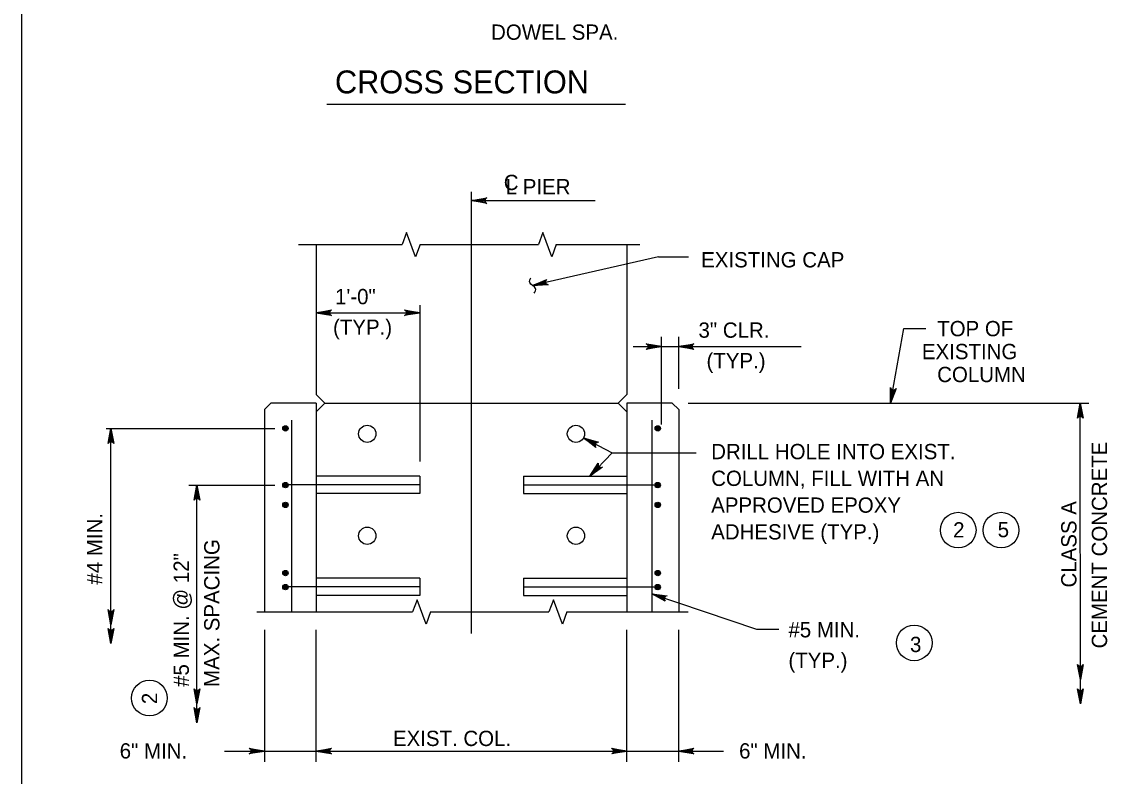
# Model space of a CAD drawing. Extents: x 646165 to 651486, y 296916 to 299292.
# Drawn here: x 650670.6 to 650883.5, y 297792.1 to 297940.1 of the extents above; entities that cross this region are included whole.
import ezdxf

# ---------------------------------------------------------------- set-up
doc = ezdxf.new("R2010")
doc.units = 0
for name, color, linetype in [('2', 7, 'Continuous'), ('50', 7, 'Continuous'), ('51', 7, 'Continuous'), ('52', 7, 'Continuous'), ('53', 7, 'Continuous'), ('54', 7, 'Continuous'), ('59', 7, 'Continuous')]:
    doc.layers.add(name, color=color, linetype=linetype)

msp = doc.modelspace()

# ---------------------------------------------------------------- linework, layer by layer
at = {"layer": '2'}
msp.add_line((650670.59, 297525.25), (650670.59, 298089.25), dxfattribs=at)
at = {"layer": '50'}
msp.add_line((650758.84, 297820.12), (650758.84, 297906.75), dxfattribs=at)
at = {"layer": '51'}
for p, q in [((650718.21, 297864.06), (650719.48, 297865.32)), ((650728.37, 297865.32), (650719.48, 297865.32)), ((650728.37, 297865.32), (650728.37, 297824.35)), ((650789.31, 297865.32), (650789.31, 297824.35)), ((650798.2, 297865.32), (650789.31, 297865.32)), ((650798.2, 297865.32), (650799.47, 297864.06)), ((650718.21, 297864.06), (650718.21, 297824.35)), ((650799.47, 297864.06), (650799.47, 297824.35)), ((650748.68, 297850.98), (650728.37, 297850.98)), ((650748.68, 297850.98), (650748.68, 297847.6)), ((650769, 297850.98), (650789.31, 297850.98)), ((650769, 297850.98), (650769, 297847.6)), ((650748.68, 297847.6), (650728.37, 297847.6)), ((650769, 297847.6), (650789.31, 297847.6)), ((650748.68, 297830.98), (650728.37, 297830.98)), ((650748.68, 297830.98), (650748.68, 297827.6)), ((650769, 297830.98), (650769, 297827.6)), ((650769, 297830.98), (650789.31, 297830.98)), ((650748.68, 297827.6), (650728.37, 297827.6)), ((650769, 297827.6), (650789.31, 297827.6))]:
    msp.add_line(p, q, dxfattribs=at)
for centre in [(650738.37, 297859.29), (650779.31, 297859.29), (650738.37, 297839.29), (650779.31, 297839.29)]:
    msp.add_circle(centre, 1.69, dxfattribs=at)
at = {"layer": '52'}
for p, q in [((650758.84, 297905.04), (650783.09, 297905.04)), ((650724.89, 297896.4), (650745.23, 297896.4)), ((650748.73, 297896.4), (650771.96, 297896.4)), ((650775.46, 297896.4), (650791.87, 297896.4)), ((650795.51, 297893.99), (650770.82, 297888.38)), ((650795.51, 297893.99), (650801.42, 297893.99)), ((650748.68, 297884.54), (650748.68, 297853.84)), ((650728.37, 297883.03), (650748.68, 297883.03)), ((650796.09, 297861.14), (650796.09, 297878.33)), ((650799.47, 297868.09), (650799.47, 297878.33)), ((650790.53, 297876.41), (650823.46, 297876.41)), ((650801.35, 297865.32), (650879.89, 297865.32)), ((650878.26, 297806.31), (650878.25, 297865.32)), ((650687.16, 297860.35), (650720.26, 297860.35)), ((650688.1, 297818.13), (650688.1, 297860.35)), ((650780.81, 297858.51), (650786.44, 297855.57)), ((650786.44, 297855.57), (650782.02, 297850.98)), ((650786.44, 297855.57), (650802.91, 297855.57)), ((650703.39, 297849.23), (650720.26, 297849.23)), ((650704.96, 297802.61), (650704.96, 297849.23)), ((650716.74, 297824.35), (650747.28, 297824.35)), ((650750.78, 297824.35), (650774.01, 297824.35)), ((650777.51, 297824.35), (650801.32, 297824.35)), ((650718.21, 297820.85), (650718.21, 297794.97)), ((650728.37, 297794.97), (650728.37, 297820.85)), ((650789.31, 297794.97), (650789.31, 297820.85)), ((650799.47, 297794.97), (650799.47, 297820.85)), ((650710.39, 297797.04), (650808.27, 297797.04))]:
    msp.add_line(p, q, dxfattribs=at)
for points in [[(650758.84, 297905.04), (650761.82, 297905.6), (650761.59, 297905.44), (650761.47, 297905.24), (650761.44, 297905.04), (650761.47, 297904.84), (650761.59, 297904.64), (650761.82, 297904.48), (650758.84, 297905.04), (650761.59, 297904.64), (650761.47, 297904.84), (650758.84, 297905.04), (650761.44, 297905.04), (650761.47, 297905.24), (650758.84, 297905.04), (650761.59, 297905.44)], [(650748.73, 297896.4), (650747.85, 297893.99), (650746.1, 297898.8), (650745.23, 297896.4)], [(650775.46, 297896.4), (650774.58, 297893.99), (650772.83, 297898.8), (650771.96, 297896.4)], [(650770.82, 297888.38), (650773.61, 297889.59), (650773.51, 297889.48), (650773.42, 297889.38), (650773.38, 297889.27), (650773.35, 297889.16), (650773.35, 297889.06), (650773.36, 297888.96), (650773.4, 297888.86), (650773.43, 297888.77), (650773.51, 297888.68), (650773.59, 297888.6), (650773.72, 297888.55), (650773.85, 297888.5), (650770.82, 297888.38), (650773.72, 297888.55), (650773.59, 297888.6), (650770.82, 297888.38), (650773.51, 297888.68), (650773.43, 297888.77), (650770.82, 297888.38), (650773.4, 297888.86), (650773.36, 297888.96), (650770.82, 297888.38), (650773.35, 297889.06), (650773.35, 297889.16), (650770.82, 297888.38), (650773.38, 297889.27), (650773.42, 297889.38), (650770.82, 297888.38), (650773.51, 297889.48)], [(650728.37, 297883.03), (650731.35, 297883.59), (650731.24, 297883.51), (650731.12, 297883.43), (650731.06, 297883.33), (650731, 297883.23), (650730.99, 297883.13), (650730.97, 297883.03), (650730.99, 297882.93), (650731, 297882.83), (650731.06, 297882.73), (650731.12, 297882.63), (650731.24, 297882.55), (650731.35, 297882.47), (650728.37, 297883.03), (650731.24, 297882.55), (650731.12, 297882.63), (650728.37, 297883.03), (650731.06, 297882.73), (650731, 297882.83), (650728.37, 297883.03), (650730.99, 297882.93), (650730.97, 297883.03), (650728.37, 297883.03), (650730.99, 297883.13), (650731, 297883.23), (650728.37, 297883.03), (650731.06, 297883.33), (650731.12, 297883.43), (650728.37, 297883.03), (650731.24, 297883.51)], [(650748.68, 297883.03), (650745.7, 297882.47), (650745.81, 297882.55), (650745.93, 297882.63), (650745.99, 297882.73), (650746.05, 297882.83), (650746.06, 297882.93), (650746.08, 297883.03), (650746.06, 297883.13), (650746.05, 297883.23), (650745.99, 297883.33), (650745.93, 297883.43), (650745.81, 297883.51), (650745.7, 297883.59), (650748.68, 297883.03), (650745.81, 297883.51), (650745.93, 297883.43), (650748.68, 297883.03), (650745.99, 297883.33), (650746.05, 297883.23), (650748.68, 297883.03), (650746.06, 297883.13), (650746.08, 297883.03), (650748.68, 297883.03), (650746.06, 297882.93), (650746.05, 297882.83), (650748.68, 297883.03), (650745.99, 297882.73), (650745.93, 297882.63), (650748.68, 297883.03), (650745.81, 297882.55)], [(650841.03, 297865.32), (650843.6, 297879.97), (650847.92, 297879.97)], [(650796.09, 297876.41), (650793.11, 297875.85), (650793.22, 297875.93), (650793.34, 297876.01), (650793.4, 297876.11), (650793.46, 297876.21), (650793.48, 297876.31), (650793.49, 297876.41), (650793.48, 297876.51), (650793.46, 297876.61), (650793.4, 297876.71), (650793.34, 297876.81), (650793.22, 297876.89), (650793.11, 297876.97), (650796.09, 297876.41), (650793.22, 297876.89), (650793.34, 297876.81), (650796.09, 297876.41), (650793.4, 297876.71), (650793.46, 297876.61), (650796.09, 297876.41), (650793.48, 297876.51), (650793.49, 297876.41), (650796.09, 297876.41), (650793.48, 297876.31), (650793.46, 297876.21), (650796.09, 297876.41), (650793.4, 297876.11), (650793.34, 297876.01), (650796.09, 297876.41), (650793.22, 297875.93)], [(650799.47, 297876.41), (650802.45, 297876.97), (650802.33, 297876.89), (650802.22, 297876.81), (650802.16, 297876.71), (650802.1, 297876.61), (650802.08, 297876.51), (650802.07, 297876.41), (650802.08, 297876.31), (650802.1, 297876.21), (650802.16, 297876.11), (650802.22, 297876.01), (650802.33, 297875.93), (650802.45, 297875.85), (650799.47, 297876.41), (650802.33, 297875.93), (650802.22, 297876.01), (650799.47, 297876.41), (650802.16, 297876.11), (650802.1, 297876.21), (650799.47, 297876.41), (650802.08, 297876.31), (650802.07, 297876.41), (650799.47, 297876.41), (650802.08, 297876.51), (650802.1, 297876.61), (650799.47, 297876.41), (650802.16, 297876.71), (650802.22, 297876.81), (650799.47, 297876.41), (650802.33, 297876.89)], [(650841.03, 297865.32), (650841, 297868.36), (650841.06, 297868.23), (650841.12, 297868.1), (650841.2, 297868.03), (650841.29, 297867.95), (650841.39, 297867.92), (650841.48, 297867.88), (650841.58, 297867.88), (650841.69, 297867.88), (650841.79, 297867.92), (650841.9, 297867.97), (650842, 297868.06), (650842.1, 297868.16), (650841.03, 297865.32), (650842, 297868.06), (650841.9, 297867.97), (650841.03, 297865.32), (650841.79, 297867.92), (650841.69, 297867.88), (650841.03, 297865.32), (650841.58, 297867.88), (650841.48, 297867.88), (650841.03, 297865.32), (650841.39, 297867.92), (650841.29, 297867.95), (650841.03, 297865.32), (650841.2, 297868.03), (650841.12, 297868.1), (650841.03, 297865.32), (650841.06, 297868.23)], [(650878.25, 297865.32), (650878.81, 297862.34), (650878.73, 297862.45), (650878.65, 297862.57), (650878.55, 297862.63), (650878.45, 297862.69), (650878.35, 297862.71), (650878.25, 297862.72), (650878.15, 297862.71), (650878.05, 297862.69), (650877.95, 297862.63), (650877.85, 297862.57), (650877.78, 297862.45), (650877.7, 297862.34), (650878.25, 297865.32), (650877.78, 297862.45), (650877.85, 297862.57), (650878.25, 297865.32), (650877.95, 297862.63), (650878.05, 297862.69), (650878.25, 297865.32), (650878.15, 297862.71), (650878.25, 297862.72), (650878.25, 297865.32), (650878.35, 297862.71), (650878.45, 297862.69), (650878.25, 297865.32), (650878.55, 297862.63), (650878.65, 297862.57), (650878.25, 297865.32), (650878.73, 297862.45)], [(650688.1, 297860.35), (650688.66, 297857.37), (650688.58, 297857.48), (650688.5, 297857.6), (650688.4, 297857.66), (650688.3, 297857.72), (650688.2, 297857.73), (650688.1, 297857.75), (650688, 297857.73), (650687.9, 297857.72), (650687.8, 297857.66), (650687.7, 297857.6), (650687.62, 297857.48), (650687.55, 297857.37), (650688.1, 297860.35), (650687.62, 297857.48), (650687.7, 297857.6), (650688.1, 297860.35), (650687.8, 297857.66), (650687.9, 297857.72), (650688.1, 297860.35), (650688, 297857.73), (650688.1, 297857.75), (650688.1, 297860.35), (650688.2, 297857.73), (650688.3, 297857.72), (650688.1, 297860.35), (650688.4, 297857.66), (650688.5, 297857.6), (650688.1, 297860.35), (650688.58, 297857.48)], [(650780.81, 297858.51), (650783.71, 297857.62), (650783.44, 297857.59), (650783.24, 297857.47), (650783.12, 297857.3), (650783.05, 297857.11), (650783.07, 297856.88), (650783.2, 297856.63), (650780.81, 297858.51), (650783.07, 297856.88), (650783.05, 297857.11), (650780.81, 297858.51), (650783.12, 297857.3), (650783.24, 297857.47), (650780.81, 297858.51), (650783.44, 297857.59)], [(650782.02, 297850.98), (650783.69, 297853.52), (650783.64, 297853.24), (650783.7, 297853.02), (650783.82, 297852.85), (650783.99, 297852.74), (650784.22, 297852.69), (650784.49, 297852.74), (650782.02, 297850.98), (650784.22, 297852.69), (650783.99, 297852.74), (650782.02, 297850.98), (650783.82, 297852.85), (650783.7, 297853.02), (650782.02, 297850.98), (650783.64, 297853.24)], [(650704.96, 297849.23), (650705.52, 297846.25), (650705.44, 297846.36), (650705.36, 297846.48), (650705.26, 297846.53), (650705.16, 297846.59), (650705.06, 297846.61), (650704.96, 297846.63), (650704.86, 297846.61), (650704.76, 297846.59), (650704.66, 297846.53), (650704.56, 297846.48), (650704.48, 297846.36), (650704.4, 297846.25), (650704.96, 297849.23), (650704.48, 297846.36), (650704.56, 297846.48), (650704.96, 297849.23), (650704.66, 297846.53), (650704.76, 297846.59), (650704.96, 297849.23), (650704.86, 297846.61), (650704.96, 297846.63), (650704.96, 297849.23), (650705.06, 297846.61), (650705.16, 297846.59), (650704.96, 297849.23), (650705.26, 297846.53), (650705.36, 297846.48), (650704.96, 297849.23), (650705.44, 297846.36)], [(650750.78, 297824.35), (650749.91, 297821.94), (650748.16, 297826.75), (650747.28, 297824.35)], [(650777.51, 297824.35), (650776.64, 297821.94), (650774.89, 297826.75), (650774.01, 297824.35)], [(650794.18, 297827.92), (650814.75, 297820.94), (650819.08, 297820.94)], [(650794.18, 297827.92), (650797.19, 297827.49), (650796.92, 297827.41), (650796.74, 297827.26), (650796.65, 297827.08), (650796.62, 297826.88), (650796.66, 297826.65), (650796.83, 297826.43), (650794.18, 297827.92), (650796.66, 297826.65), (650796.62, 297826.88), (650794.18, 297827.92), (650796.65, 297827.08), (650796.74, 297827.26), (650794.18, 297827.92), (650796.92, 297827.41)], [(650688.1, 297821.82), (650687.55, 297824.8), (650687.62, 297824.69), (650687.7, 297824.57), (650687.8, 297824.51), (650687.9, 297824.45), (650688, 297824.44), (650688.1, 297824.42), (650688.2, 297824.44), (650688.3, 297824.45), (650688.4, 297824.51), (650688.5, 297824.57), (650688.58, 297824.69), (650688.66, 297824.8), (650688.1, 297821.82), (650688.58, 297824.69), (650688.5, 297824.57), (650688.1, 297821.82), (650688.4, 297824.51), (650688.3, 297824.45), (650688.1, 297821.82), (650688.2, 297824.44), (650688.1, 297824.42), (650688.1, 297821.82), (650688, 297824.44), (650687.9, 297824.45), (650688.1, 297821.82), (650687.8, 297824.51), (650687.7, 297824.57), (650688.1, 297821.82), (650687.62, 297824.69)], [(650688.1, 297818.13), (650687.55, 297821.11), (650687.62, 297821), (650687.7, 297820.88), (650687.8, 297820.82), (650687.9, 297820.76), (650688, 297820.75), (650688.1, 297820.73), (650688.2, 297820.75), (650688.3, 297820.76), (650688.4, 297820.82), (650688.5, 297820.88), (650688.58, 297821), (650688.66, 297821.11), (650688.1, 297818.13), (650688.58, 297821), (650688.5, 297820.88), (650688.1, 297818.13), (650688.4, 297820.82), (650688.3, 297820.76), (650688.1, 297818.13), (650688.2, 297820.75), (650688.1, 297820.73), (650688.1, 297818.13), (650688, 297820.75), (650687.9, 297820.76), (650688.1, 297818.13), (650687.8, 297820.82), (650687.7, 297820.88), (650688.1, 297818.13), (650687.62, 297821)], [(650878.26, 297811.08), (650877.7, 297814.06), (650877.78, 297813.95), (650877.86, 297813.83), (650877.96, 297813.77), (650878.06, 297813.71), (650878.16, 297813.7), (650878.26, 297813.68), (650878.36, 297813.7), (650878.46, 297813.71), (650878.56, 297813.77), (650878.66, 297813.83), (650878.73, 297813.95), (650878.81, 297814.06), (650878.26, 297811.08), (650878.73, 297813.95), (650878.66, 297813.83), (650878.26, 297811.08), (650878.56, 297813.77), (650878.46, 297813.71), (650878.26, 297811.08), (650878.36, 297813.7), (650878.26, 297813.68), (650878.26, 297811.08), (650878.16, 297813.7), (650878.06, 297813.71), (650878.26, 297811.08), (650877.96, 297813.77), (650877.86, 297813.83), (650878.26, 297811.08), (650877.78, 297813.95)], [(650704.96, 297806.3), (650704.4, 297809.28), (650704.48, 297809.17), (650704.56, 297809.05), (650704.66, 297808.99), (650704.76, 297808.93), (650704.86, 297808.92), (650704.96, 297808.9), (650705.06, 297808.92), (650705.16, 297808.93), (650705.26, 297808.99), (650705.36, 297809.05), (650705.44, 297809.17), (650705.52, 297809.28), (650704.96, 297806.3), (650705.44, 297809.17), (650705.36, 297809.05), (650704.96, 297806.3), (650705.26, 297808.99), (650705.16, 297808.93), (650704.96, 297806.3), (650705.06, 297808.92), (650704.96, 297808.9), (650704.96, 297806.3), (650704.86, 297808.92), (650704.76, 297808.93), (650704.96, 297806.3), (650704.66, 297808.99), (650704.56, 297809.05), (650704.96, 297806.3), (650704.48, 297809.17)], [(650878.26, 297806.31), (650877.7, 297809.29), (650877.78, 297809.18), (650877.86, 297809.06), (650877.96, 297809), (650878.06, 297808.95), (650878.16, 297808.93), (650878.26, 297808.91), (650878.36, 297808.93), (650878.46, 297808.95), (650878.56, 297809), (650878.66, 297809.06), (650878.73, 297809.18), (650878.81, 297809.29), (650878.26, 297806.31), (650878.73, 297809.18), (650878.66, 297809.06), (650878.26, 297806.31), (650878.56, 297809), (650878.46, 297808.95), (650878.26, 297806.31), (650878.36, 297808.93), (650878.26, 297808.91), (650878.26, 297806.31), (650878.16, 297808.93), (650878.06, 297808.95), (650878.26, 297806.31), (650877.96, 297809), (650877.86, 297809.06), (650878.26, 297806.31), (650877.78, 297809.18)], [(650704.96, 297802.61), (650704.4, 297805.59), (650704.48, 297805.48), (650704.56, 297805.36), (650704.66, 297805.3), (650704.76, 297805.24), (650704.86, 297805.22), (650704.96, 297805.21), (650705.06, 297805.22), (650705.16, 297805.24), (650705.26, 297805.3), (650705.36, 297805.36), (650705.44, 297805.48), (650705.52, 297805.59), (650704.96, 297802.61), (650705.44, 297805.48), (650705.36, 297805.36), (650704.96, 297802.61), (650705.26, 297805.3), (650705.16, 297805.24), (650704.96, 297802.61), (650705.06, 297805.22), (650704.96, 297805.21), (650704.96, 297802.61), (650704.86, 297805.22), (650704.76, 297805.24), (650704.96, 297802.61), (650704.66, 297805.3), (650704.56, 297805.36), (650704.96, 297802.61), (650704.48, 297805.48)], [(650718.21, 297797.04), (650715.23, 297796.48), (650715.34, 297796.56), (650715.46, 297796.64), (650715.52, 297796.74), (650715.58, 297796.84), (650715.59, 297796.94), (650715.61, 297797.04), (650715.59, 297797.14), (650715.58, 297797.24), (650715.52, 297797.34), (650715.46, 297797.44), (650715.34, 297797.52), (650715.23, 297797.6), (650718.21, 297797.04), (650715.34, 297797.52), (650715.46, 297797.44), (650718.21, 297797.04), (650715.52, 297797.34), (650715.58, 297797.24), (650718.21, 297797.04), (650715.59, 297797.14), (650715.61, 297797.04), (650718.21, 297797.04), (650715.59, 297796.94), (650715.58, 297796.84), (650718.21, 297797.04), (650715.52, 297796.74), (650715.46, 297796.64), (650718.21, 297797.04), (650715.34, 297796.56)], [(650728.37, 297797.04), (650731.35, 297797.6), (650731.24, 297797.52), (650731.12, 297797.44), (650731.06, 297797.34), (650731, 297797.24), (650730.99, 297797.14), (650730.97, 297797.04), (650730.99, 297796.94), (650731, 297796.84), (650731.06, 297796.74), (650731.12, 297796.64), (650731.24, 297796.56), (650731.35, 297796.48), (650728.37, 297797.04), (650731.24, 297796.56), (650731.12, 297796.64), (650728.37, 297797.04), (650731.06, 297796.74), (650731, 297796.84), (650728.37, 297797.04), (650730.99, 297796.94), (650730.97, 297797.04), (650728.37, 297797.04), (650730.99, 297797.14), (650731, 297797.24), (650728.37, 297797.04), (650731.06, 297797.34), (650731.12, 297797.44), (650728.37, 297797.04), (650731.24, 297797.52)], [(650789.31, 297797.04), (650786.33, 297796.48), (650786.44, 297796.56), (650786.56, 297796.64), (650786.62, 297796.74), (650786.67, 297796.84), (650786.69, 297796.94), (650786.71, 297797.04), (650786.69, 297797.14), (650786.67, 297797.24), (650786.62, 297797.34), (650786.56, 297797.44), (650786.44, 297797.52), (650786.33, 297797.6), (650789.31, 297797.04), (650786.44, 297797.52), (650786.56, 297797.44), (650789.31, 297797.04), (650786.62, 297797.34), (650786.67, 297797.24), (650789.31, 297797.04), (650786.69, 297797.14), (650786.71, 297797.04), (650789.31, 297797.04), (650786.69, 297796.94), (650786.67, 297796.84), (650789.31, 297797.04), (650786.62, 297796.74), (650786.56, 297796.64), (650789.31, 297797.04), (650786.44, 297796.56)], [(650799.47, 297797.04), (650802.45, 297797.6), (650802.33, 297797.52), (650802.22, 297797.44), (650802.16, 297797.34), (650802.1, 297797.24), (650802.08, 297797.14), (650802.07, 297797.04), (650802.08, 297796.94), (650802.1, 297796.84), (650802.16, 297796.74), (650802.22, 297796.64), (650802.33, 297796.56), (650802.45, 297796.48), (650799.47, 297797.04), (650802.33, 297796.56), (650802.22, 297796.64), (650799.47, 297797.04), (650802.16, 297796.74), (650802.1, 297796.84), (650799.47, 297797.04), (650802.08, 297796.94), (650802.07, 297797.04), (650799.47, 297797.04), (650802.08, 297797.14), (650802.1, 297797.24), (650799.47, 297797.04), (650802.16, 297797.34), (650802.22, 297797.44), (650799.47, 297797.04), (650802.33, 297797.52)]]:
    msp.add_lwpolyline(points, dxfattribs=at)
for centre in [(650854.29, 297840.39), (650862.71, 297840.39), (650845.67, 297818.28), (650695.64, 297807.45)]:
    msp.add_circle(centre, 3.5, dxfattribs=at)
msp.add_spline([(650771.13, 297886.85), (650771.39, 297887.8), (650770.24, 297888.97), (650770.46, 297889.89)], degree=3, dxfattribs=at)
at = {"layer": '53'}
msp.add_line((650730.47, 297923.99), (650789.04, 297923.99), dxfattribs=at)
at = {"layer": '54'}
for p, q in [((650723.49, 297861.99), (650723.49, 297824.35)), ((650794.18, 297861.99), (650794.18, 297824.35)), ((650748.68, 297849.29), (650722.32, 297849.29)), ((650769, 297849.29), (650795.35, 297849.29)), ((650748.68, 297829.29), (650722.32, 297829.29)), ((650769, 297829.29), (650795.35, 297829.29))]:
    msp.add_line(p, q, dxfattribs=at)
for centre, radius in [((650722.32, 297860.35), 0.533), ((650722.32, 297860.35), 0.4), ((650722.32, 297860.35), 0.267), ((650722.32, 297860.35), 0.133), ((650795.36, 297860.35), 0.533), ((650795.36, 297860.35), 0.4), ((650795.36, 297860.35), 0.267), ((650795.36, 297860.35), 0.133), ((650722.32, 297849.22), 0.533), ((650722.32, 297849.22), 0.4), ((650722.32, 297849.22), 0.267), ((650722.32, 297849.22), 0.133), ((650795.35, 297849.22), 0.533), ((650795.35, 297849.22), 0.4), ((650795.35, 297849.22), 0.267), ((650795.35, 297849.22), 0.133), ((650722.32, 297845.35), 0.533), ((650722.32, 297845.35), 0.4), ((650722.32, 297845.35), 0.267), ((650722.32, 297845.35), 0.133), ((650795.36, 297845.35), 0.533), ((650795.36, 297845.35), 0.4), ((650795.36, 297845.35), 0.267), ((650795.36, 297845.35), 0.133), ((650722.32, 297831.97), 0.533), ((650722.32, 297831.97), 0.4), ((650795.36, 297831.97), 0.533), ((650795.36, 297831.97), 0.4), ((650722.32, 297831.97), 0.267), ((650722.32, 297831.97), 0.133), ((650795.36, 297831.97), 0.267), ((650795.36, 297831.97), 0.133), ((650722.32, 297829.22), 0.533), ((650722.32, 297829.22), 0.4), ((650722.32, 297829.22), 0.267), ((650722.32, 297829.22), 0.133), ((650795.35, 297829.22), 0.533), ((650795.35, 297829.22), 0.4), ((650795.35, 297829.22), 0.267), ((650795.35, 297829.22), 0.133)]:
    msp.add_circle(centre, radius, dxfattribs=at)
at = {"layer": '59'}
for p, q in [((650728.37, 297896.4), (650728.37, 297867.01)), ((650789.31, 297896.4), (650789.31, 297867.01)), ((650730.06, 297865.32), (650728.37, 297867.01)), ((650789.31, 297867.01), (650787.62, 297865.32)), ((650730.06, 297865.32), (650728.37, 297863.63)), ((650730.06, 297865.32), (650787.62, 297865.32)), ((650789.31, 297863.63), (650787.62, 297865.32))]:
    msp.add_line(p, q, dxfattribs=at)

# ---------------------------------------------------------------- texts
at = {"layer": '53'}
for s, height, p in [('DOWEL SPA.', 3, (650762.66, 297936.59)), ('CROSS SECTION', 4.5, (650732.04, 297926.07)), ('C', 3, (650765.15, 297907.11)), ('L PIER', 3, (650765.53, 297906.27)), ('EXISTING CAP', 3, (650803.87, 297891.93)), ('1\'-0"', 3, (650732.05, 297884.71)), ('(TYP.)', 3, (650731.66, 297878.71)), ('TOP OF', 3, (650850.17, 297878.43)), ('3" CLR.', 3, (650803.35, 297878.14)), ('EXISTING', 3, (650847.17, 297873.93)), ('(TYP.)', 3, (650804.92, 297872.14)), ('COLUMN', 3, (650850.17, 297869.43)), ('DRILL HOLE INTO EXIST.', 3, (650805.84, 297854.31)), ('COLUMN, FILL WITH AN', 3, (650805.84, 297849.06)), ('APPROVED EPOXY', 3, (650805.84, 297843.81)), ('ADHESIVE (TYP.)', 3, (650805.84, 297838.56)), ('2', 3, (650853.3, 297838.95)), ('5', 3, (650862.04, 297839)), ('#5 MIN.', 3, (650820.99, 297819.36)), ('3', 3, (650844.84, 297816.47)), ('(TYP.)', 3, (650820.99, 297813.36)), ('EXIST. COL.', 3, (650743.41, 297798.04)), ('6" MIN.', 3, (650689.81, 297795.59)), ('6" MIN.', 3, (650811.31, 297795.59))]:
    msp.add_text(s, height=height, dxfattribs=at).set_placement(p)
for s, p in [('CEMENT CONCRETE', (650883.5, 297817.19)), ('CLASS A', (650877.5, 297829.14)), ('#4 MIN.', (650686.39, 297829.71)), ('MAX. SPACING', (650709.38, 297809.64)), ('#5 MIN. @ 12"', (650703.38, 297809.64)), ('2', (650697.16, 297806.26))]:
    msp.add_text(s, height=3, rotation=90, dxfattribs=at).set_placement(p)

doc.saveas('drawing.dxf')
